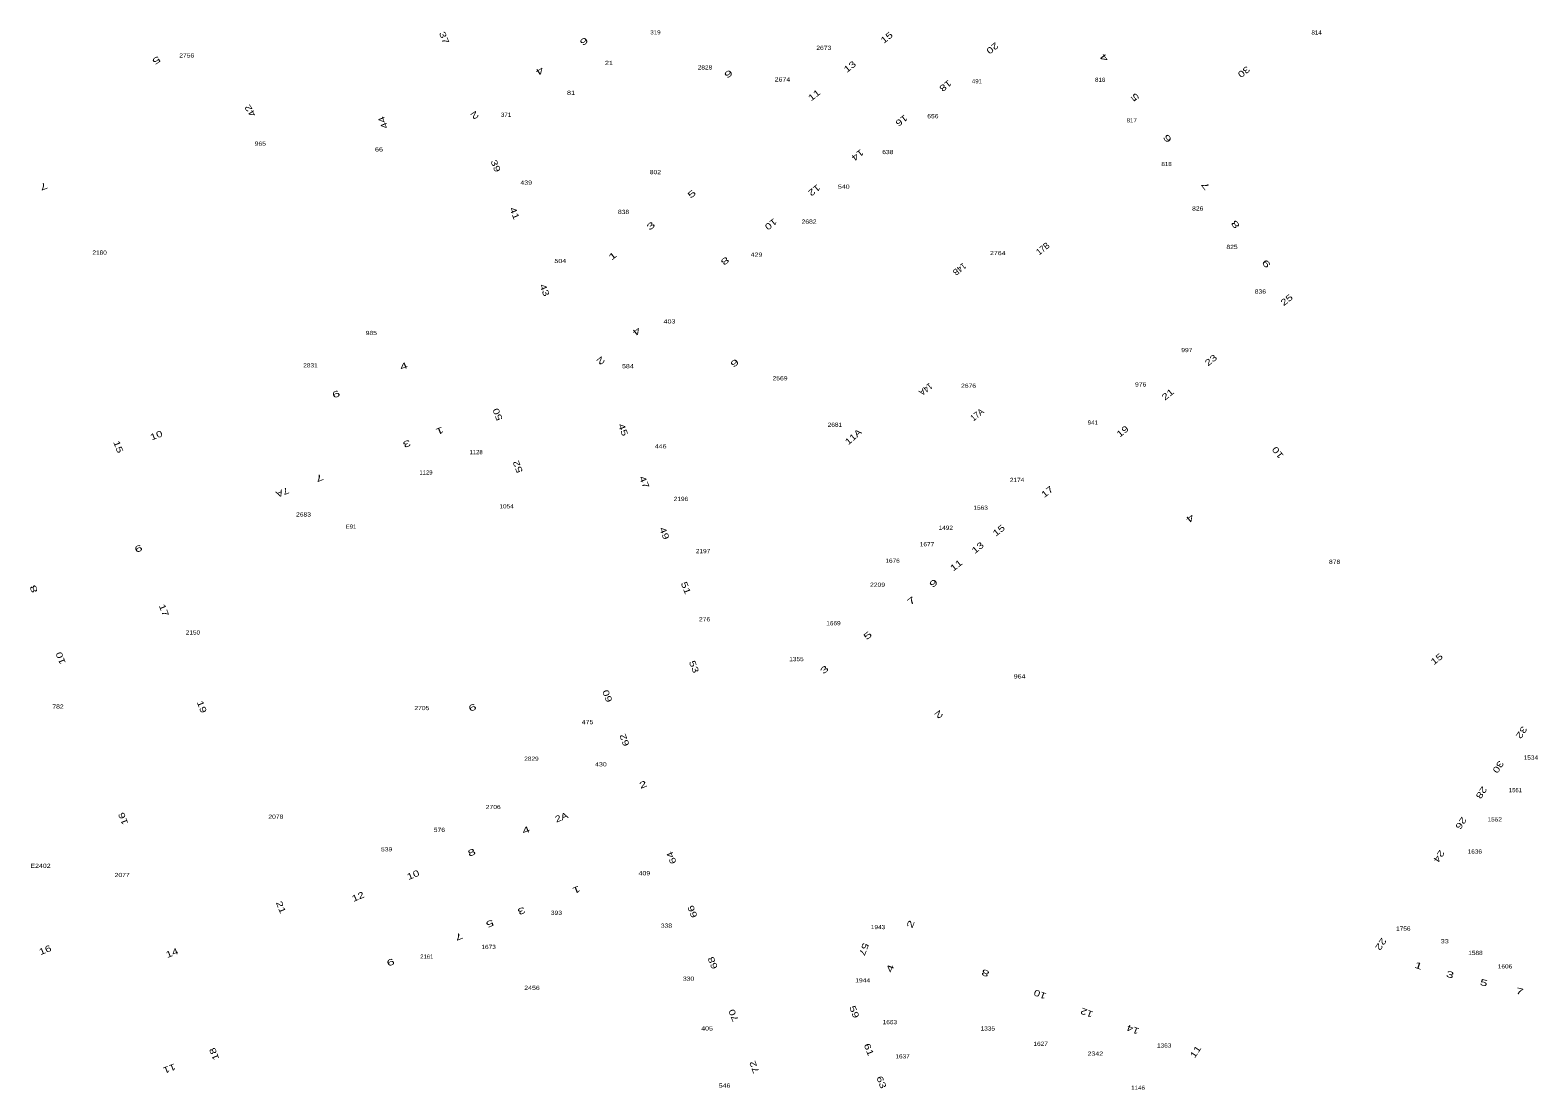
# Model space of a CAD drawing. Extents: x -828673 to -815583, y -1077737 to -1063807.
# Drawn here: x -821832.5 to -821473.2, y -1071355.2 to -1071102.6 of the extents above; entities that cross this region are included whole.
import ezdxf
from ezdxf.enums import TextEntityAlignment as Align

# ---------------------------------------------------------------- set-up
doc = ezdxf.new("R2010")
doc.units = 0
doc.header["$LTSCALE"] = 0.4
doc.layers.add('1', color=7, linetype='Continuous')
doc.layers.add('2', color=7, linetype='Continuous')

msp = doc.modelspace()

# ---------------------------------------------------------------- texts
at = {"layer": '1'}
for s, width, p in [('319', 1.1, (-821683.492, -1071103.658)), ('814', 1.1, (-821525.922, -1071103.687)), ('2756', 1.2, (-821795.197, -1071109.174)), ('2673', 1.2, (-821643.373, -1071107.358)), ('21', 1.3, (-821694.564, -1071110.951)), ('2828', 1.15, (-821671.69, -1071112.02)), ('2674', 1.25, (-821653.223, -1071114.887)), ('491', 1.1, (-821606.867, -1071115.322)), ('816', 1.1, (-821577.505, -1071114.974)), ('81', 1.3, (-821703.609, -1071118.064)), ('371', 1.1, (-821719.091, -1071123.306)), ('656', 1.2, (-821617.377, -1071123.645)), ('817', 1.1, (-821569.991, -1071124.639)), ('965', 1.2, (-821777.653, -1071130.189)), ('66', 1.3, (-821749.376, -1071131.56)), ('638', 1.2, (-821628.112, -1071132.192)), ('818', 1.1, (-821561.685, -1071135.038)), ('802', 1.2, (-821683.498, -1071136.969)), ('439', 1.25, (-821714.292, -1071139.475)), ('540', 1.25, (-821638.604, -1071140.443)), ('826', 1.2, (-821554.26, -1071145.644)), ('838', 1.2, (-821691.086, -1071146.452)), ('2682', 1.2, (-821646.878, -1071148.766)), ('2180', 1.15, (-821815.95, -1071156.15)), ('429', 1.25, (-821659.402, -1071156.641)), ('2764', 1.25, (-821601.897, -1071156.264)), ('825', 1.2, (-821546.073, -1071154.801)), ('504', 1.25, (-821706.175, -1071158.159)), ('836', 1.2, (-821539.325, -1071165.435)), ('403', 1.25, (-821680.138, -1071172.544)), ('985', 1.2, (-821751.206, -1071175.305)), ('997', 1.2, (-821556.847, -1071179.38)), ('2831', 1.15, (-821765.71, -1071183.01)), ('584', 1.25, (-821690.062, -1071183.229)), ('2569', 1.2, (-821653.795, -1071186.103)), ('2676', 1.2, (-821608.874, -1071187.873)), ('976', 1.2, (-821567.849, -1071187.569)), ('2681', 1.15, (-821640.718, -1071197.181)), ('941', 1.1, (-821579.254, -1071196.652)), ('446', 1.25, (-821682.24, -1071202.313)), ('1128', 1.05, (-821726.23, -1071203.704)), ('1129', 1.05, (-821738.179, -1071208.564)), ('2174', 1.15, (-821597.305, -1071210.322)), ('1054', 1.15, (-821718.971, -1071216.609)), ('2196', 1.15, (-821677.41, -1071214.842)), ('1563', 1.15, (-821605.982, -1071216.944)), ('2683', 1.2, (-821767.366, -1071218.549)), ('E91', 1.05, (-821756.031, -1071221.454)), ('1492', 1.15, (-821614.301, -1071221.732)), ('2197', 1.15, (-821672.139, -1071227.291)), ('1677', 1.15, (-821618.767, -1071225.659)), ('1676', 1.15, (-821626.98, -1071229.577)), ('878', 1.2, (-821521.63, -1071229.84)), ('2209', 1.2, (-821630.558, -1071235.305)), ('276', 1.2, (-821671.781, -1071243.535)), ('1669', 1.15, (-821641.068, -1071244.478)), ('2150', 1.15, (-821793.703, -1071246.679)), ('1355', 1.15, (-821649.879, -1071253.025)), ('964', 1.25, (-821596.717, -1071257.148)), ('782', 1.2, (-821825.869, -1071264.342)), ('2705', 1.2, (-821739.157, -1071264.694)), ('475', 1.25, (-821699.67, -1071268.035)), ('2829', 1.15, (-821713.04, -1071276.76)), ('430', 1.25, (-821696.487, -1071278.09)), ('1534', 1.15, (-821474.866, -1071276.485)), ('1561', 1.05, (-821478.551, -1071284.259)), ('2706', 1.2, (-821722.147, -1071288.274)), ('2078', 1.2, (-821773.961, -1071290.585)), ('1552', 1.15, (-821483.474, -1071291.217)), ('576', 1.2, (-821734.986, -1071293.713)), ('539', 1.2, (-821747.55, -1071298.35)), ('1636', 1.15, (-821488.22, -1071298.886)), ('E2402', 1.25, (-821830.044, -1071302.294)), ('2077', 1.2, (-821810.58, -1071304.471)), ('409', 1.25, (-821686.111, -1071304.049)), ('393', 1.2, (-821707.091, -1071313.489)), ('338', 1.2, (-821680.873, -1071316.538)), ('1943', 1.15, (-821630.437, -1071316.887)), ('1756', 1.15, (-821505.258, -1071317.234)), ('1673', 1.15, (-821723.245, -1071321.619)), ('33', 1.3, (-821495.396, -1071320.265)), ('2161', 1.05, (-821737.98, -1071323.921)), ('1588', 1.15, (-821488.064, -1071323.041)), ('1606', 1.15, (-821481.019, -1071326.254)), ('2456', 1.25, (-821712.916, -1071331.366)), ('330', 1.2, (-821675.594, -1071329.186)), ('1944', 1.2, (-821634.09, -1071329.582)), ('1663', 1.15, (-821627.631, -1071339.54)), ('405', 1.25, (-821671.188, -1071341.038)), ('1335', 1.15, (-821604.281, -1071341.054)), ('1627', 1.15, (-821591.685, -1071344.708)), ('2342', 1.25, (-821578.668, -1071347.05)), ('1363', 1.15, (-821562.25, -1071345.113)), ('1637', 1.15, (-821624.588, -1071347.691)), ('546', 1.25, (-821667.027, -1071354.653)), ('1146', 1.1, (-821568.474, -1071355.165))]:
    msp.add_text(s, height=1, dxfattribs=dict(at, width=width)).set_placement(p, align=Align.CENTER)
at = {"layer": '2'}
for s, rotation, width, p in [('37', 291.749, 1.35, (-821734.5374, -1071104.7356)), ('6', 214.017, 1.7, (-821700.9399, -1071104.7095)), ('15', 38.644, 1.35, (-821627.9174, -1071104.9936)), ('5', 213.443, 1.7, (-821802.8222, -1071109.2218)), ('20', 219.113, 1.35, (-821603.6394, -1071106.3727)), ('4', 127.922, 1.7, (-821576.0095, -1071108.7789)), ('4', 213.703, 1.7, (-821711.4433, -1071111.7798)), ('9', 35.254, 1.7, (-821665.6609, -1071113.6951)), ('13', 38.706, 1.35, (-821636.704, -1071111.93)), ('30', 218.446, 1.35, (-821543.7147, -1071112.016)), ('18', 218.552, 1.35, (-821614.8256, -1071115.3178)), ('11', 38.356, 1.35, (-821645.2099, -1071118.714)), ('5', 128.252, 1.7, (-821568.6313, -1071118.1778)), ('42', 124.208, 1.35, (-821779.4522, -1071121.4461)), ('44', 111.397, 1.35, (-821747.7177, -1071124.4096)), ('2', 214.071, 1.7, (-821726.9643, -1071122.3082)), ('16', 218.04, 1.35, (-821625.2928, -1071123.5909)), ('6', 128.362, 1.7, (-821560.9074, -1071127.9965)), ('39', 292.089, 1.35, (-821722.246, -1071135.2585)), ('14', 218.517, 1.35, (-821635.7559, -1071131.8298)), ('7', 201.557, 1.65, (-821829.5454, -1071139.1943)), ('5', 38.3, 1.7, (-821674.3753, -1071142.2691)), ('12', 218.814, 1.35, (-821646.1129, -1071140.216)), ('7', 128.165, 1.7, (-821551.8268, -1071139.3135)), ('41', 291.446, 1.35, (-821717.7602, -1071146.5558)), ('3', 38.616, 1.7, (-821684.1321, -1071149.8594)), ('10', 218.694, 1.35, (-821656.4461, -1071148.3147)), ('8', 128.569, 1.7, (-821544.7176, -1071148.4871)), ('17B', 38.437, 0.95, (-821590.6982, -1071155.2769)), ('1', 38.767, 1.7, (-821693.2326, -1071157.0304)), ('8', 218.511, 1.7, (-821667.3785, -1071157.0728)), ('14B', 218.667, 0.95, (-821611.4954, -1071159.0454)), ('9', 128.704, 1.7, (-821537.3428, -1071157.858)), ('43', 291.494, 1.35, (-821710.6029, -1071164.8477)), ('25', 38.407, 1.35, (-821532.5954, -1071167.5226)), ('4', 218.579, 1.7, (-821688.4288, -1071173.8717)), ('2', 218.72, 1.7, (-821696.9649, -1071180.843)), ('23', 38.712, 1.35, (-821550.6531, -1071181.8688)), ('4', 21.207, 1.65, (-821743.2158, -1071183.4112)), ('6', 218.241, 1.7, (-821665.0833, -1071181.3862)), ('14A', 217.719, 0.95, (-821619.5182, -1071187.6483)), ('6', 21.379, 1.65, (-821759.3324, -1071190.0944)), ('21', 38.686, 1.35, (-821560.9218, -1071190.0335)), ('50', 111.367, 1.35, (-821720.413, -1071193.9443)), ('17A', 38.668, 0.95, (-821606.3836, -1071194.8586)), ('10', 20.998, 1.35, (-821802.1692, -1071199.8983)), ('1', 201.574, 1.65, (-821735.1457, -1071197.4257)), ('45', 290.961, 1.35, (-821691.8854, -1071198.1237)), ('11A', 41.596, 1.25, (-821635.8444, -1071200.1101)), ('19', 38.704, 1.35, (-821571.7, -1071198.8481)), ('15', 291.466, 1.35, (-821812.1897, -1071202.1955)), ('3', 201.383, 1.65, (-821743.0065, -1071200.5157)), ('10', 128.29, 1.35, (-821534.5947, -1071202.8647)), ('52', 111.563, 1.35, (-821715.6118, -1071206.4031)), ('7', 201.433, 1.65, (-821763.8169, -1071208.6563)), ('47', 292.366, 1.35, (-821686.8289, -1071210.6296)), ('7A', 201.323, 1.3, (-821772.6483, -1071212.1013)), ('17', 38.666, 1.35, (-821589.6601, -1071213.2327)), ('4', 218.182, 1.7, (-821556.5124, -1071218.411)), ('49', 291.298, 1.35, (-821682.0488, -1071222.8011)), ('15', 38.549, 1.35, (-821601.1984, -1071222.4523)), ('9', 201.498, 1.65, (-821806.9617, -1071225.5013)), ('13', 39.527, 1.35, (-821606.2133, -1071226.5605)), ('11', 38.539, 1.35, (-821611.3543, -1071230.7656)), ('51', 291.208, 1.35, (-821676.921, -1071235.8422)), ('9', 38.859, 1.7, (-821616.7661, -1071235.0497)), ('8', 111.213, 1.65, (-821830.9689, -1071235.5359)), ('7', 38.68, 1.7, (-821622.0442, -1071239.2119)), ('17', 291.539, 1.35, (-821801.3226, -1071241.1517)), ('5', 37.883, 1.7, (-821632.462, -1071247.4974)), ('10', 111.221, 1.35, (-821824.5373, -1071252.029)), ('15', 38.058, 1.35, (-821496.8358, -1071253.102)), ('53', 291.378, 1.35, (-821674.9898, -1071254.6226)), ('3', 39.468, 1.7, (-821642.7562, -1071255.6295)), ('60', 111.583, 1.35, (-821694.2513, -1071261.0524)), ('19', 291.539, 1.35, (-821792.2776, -1071264.1607)), ('6', 21.075, 1.65, (-821726.8427, -1071264.7805)), ('2', 218.446, 1.7, (-821616.3937, -1071265.1573)), ('62', 110.997, 1.35, (-821690.1727, -1071271.5532)), ('32', 236.52, 1.35, (-821477.7111, -1071269.5993)), ('30', 236.327, 1.35, (-821483.2599, -1071277.8162)), ('2', 21.441, 1.65, (-821686.1882, -1071283.1226)), ('28', 236.609, 1.35, (-821487.2612, -1071283.9317)), ('16', 111.213, 1.35, (-821809.6522, -1071290.2839)), ('2A', 21.762, 1.3, (-821705.6101, -1071290.9016)), ('26', 236.545, 1.35, (-821492.1098, -1071291.214)), ('4', 21.665, 1.65, (-821714.0739, -1071293.954)), ('8', 21.145, 1.65, (-821727.0315, -1071299.3072)), ('64', 111.822, 1.35, (-821678.9775, -1071299.6078)), ('24', 236.502, 1.35, (-821497.3676, -1071299.1021)), ('10', 21.801, 1.35, (-821740.966, -1071304.6312)), ('1', 201.434, 1.65, (-821702.5739, -1071306.8013)), ('12', 23.189, 1.35, (-821754.0808, -1071309.8225)), ('21', 291.376, 1.35, (-821773.4208, -1071311.9306)), ('3', 201.494, 1.65, (-821715.6817, -1071311.8413)), ('66', 111.192, 1.35, (-821673.9797, -1071312.4376)), ('5', 201.958, 1.65, (-821723.2185, -1071314.8816)), ('2', 69.444, 1.65, (-821621.9926, -1071315.9553)), ('16', 22.042, 1.35, (-821828.662, -1071322.5432)), ('7', 201.881, 1.65, (-821730.612, -1071317.9664)), ('57', 249.001, 1.35, (-821634.5177, -1071321.4117)), ('22', 236.586, 1.35, (-821511.2288, -1071320.0425)), ('14', 21.222, 1.35, (-821798.434, -1071323.2346)), ('9', 200.749, 1.65, (-821746.8658, -1071324.0794)), ('68', 111.657, 1.35, (-821669.1452, -1071324.6458)), ('4', 69.429, 1.65, (-821626.8624, -1071326.4955)), ('8', 158.934, 1.65, (-821604.6029, -1071326.6524)), ('1', 341.085, 1.65, (-821501.8986, -1071326.2984)), ('3', 344.195, 1.65, (-821494.3238, -1071328.4188)), ('10', 159.321, 1.35, (-821591.5762, -1071331.7304)), ('5', 346.064, 1.65, (-821486.2541, -1071330.3768)), ('7', 346.913, 1.65, (-821477.7123, -1071332.4154)), ('59', 291.334, 1.35, (-821636.7958, -1071336.8711)), ('70', 112.439, 1.35, (-821664.1988, -1071337.1523)), ('12', 159.529, 1.35, (-821580.4317, -1071336.0886)), ('14', 159.114, 1.35, (-821569.4446, -1071340.0971)), ('18', 111.243, 1.35, (-821787.9617, -1071346.3587)), ('61', 291.704, 1.35, (-821633.3205, -1071345.8591)), ('11', 56.244, 1.35, (-821554.164, -1071346.5257)), ('11', 201.198, 1.35, (-821799.5713, -1071349.4138)), ('72', 110.651, 1.35, (-821659.245, -1071349.4935)), ('63', 291.682, 1.35, (-821630.3252, -1071353.6339))]:
    msp.add_text(s, height=1.5, rotation=rotation, dxfattribs=dict(at, width=width)).set_placement(p, align=Align.CENTER)

doc.saveas('drawing.dxf')
